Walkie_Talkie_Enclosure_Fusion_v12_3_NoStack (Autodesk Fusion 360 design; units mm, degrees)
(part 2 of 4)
sketch "Volume Down Switch Cage Anchor Sketch (1)" plane through (0, 0, 0) normal (0, 0, 1) x axis (1, 0, 0)
  line L1 (-31.5, -1.65) -> (-32, -1.65)
  line L2 (-31.15, -0.8) -> (-31.15, -1.3)
  line L3 (-32, -0.45) -> (-31.5, -0.45)
  line L4 (-32.35, -1.3) -> (-32.35, -0.8)
  arc A1 centre (-31.5, -1.3) radius 0.35 clockwise from (-31.15, -1.3) to (-31.5, -1.65)
  arc A2 centre (-31.5, -0.8) radius 0.35 clockwise from (-31.5, -0.45) to (-31.15, -0.8)
  arc A3 centre (-32, -0.8) radius 0.35 clockwise from (-32.35, -0.8) to (-32, -0.45)
  arc A4 centre (-32, -1.3) radius 0.35 clockwise from (-32, -1.65) to (-32.35, -1.3)
extrude "Extrude66" add sketch "Volume Down Switch Cage Anchor Sketch (1)" blind 5.59 from offset 2
sketch "Volume Down Switch Floor Sketch" plane through (0, 0, 0) normal (0, 0, 1) x axis (1, 0, 0)
  line L1 (-31.55, -11.35) -> (-36.65, -11.35)
  line L2 (-31.1, -1.1) -> (-31.1, -10.9)
  line L3 (-36.65, -0.65) -> (-31.55, -0.65)
  line L4 (-37.1, -10.9) -> (-37.1, -1.1)
  arc A1 centre (-31.55, -10.9) radius 0.45 clockwise from (-31.1, -10.9) to (-31.55, -11.35)
  arc A2 centre (-31.55, -1.1) radius 0.45 clockwise from (-31.55, -0.65) to (-31.1, -1.1)
  arc A3 centre (-36.65, -1.1) radius 0.45 clockwise from (-37.1, -1.1) to (-36.65, -0.65)
  arc A4 centre (-36.65, -10.9) radius 0.45 clockwise from (-36.65, -11.35) to (-37.1, -10.9)
extrude "Extrude67" add sketch "Volume Down Switch Floor Sketch" blind 0.55 from offset 7.49
sketch "Volume Down Switch Inward Backstop Sketch" plane through (0, 0, 0) normal (0, 0, 1) x axis (1, 0, 0)
  line L1 (-31.65, -11.35) -> (-31.85, -11.35)
  line L2 (-31.3, -1) -> (-31.3, -11)
  line L3 (-31.85, -0.65) -> (-31.65, -0.65)
  line L4 (-32.2, -11) -> (-32.2, -1)
  arc A1 centre (-31.65, -11) radius 0.35 clockwise from (-31.3, -11) to (-31.65, -11.35)
  arc A2 centre (-31.65, -1) radius 0.35 clockwise from (-31.65, -0.65) to (-31.3, -1)
  arc A3 centre (-31.85, -1) radius 0.35 clockwise from (-32.2, -1) to (-31.85, -0.65)
  arc A4 centre (-31.85, -11) radius 0.35 clockwise from (-31.85, -11.35) to (-32.2, -11)
extrude "Extrude68" add sketch "Volume Down Switch Inward Backstop Sketch" blind 4.51 from offset 7.49
sketch "Volume Down Switch Side Rail Sketch" plane through (0, 0, 0) normal (0, 0, 1) x axis (1, 0, 0)
  line L1 (-32.325, -11.35) -> (-36.675, -11.35)
  line L2 (-32.025, -10.85) -> (-32.025, -11.05)
  line L3 (-36.675, -10.55) -> (-32.325, -10.55)
  line L4 (-36.975, -11.05) -> (-36.975, -10.85)
  arc A1 centre (-32.325, -11.05) radius 0.3 clockwise from (-32.025, -11.05) to (-32.325, -11.35)
  arc A2 centre (-32.325, -10.85) radius 0.3 clockwise from (-32.325, -10.55) to (-32.025, -10.85)
  arc A3 centre (-36.675, -10.85) radius 0.3 clockwise from (-36.975, -10.85) to (-36.675, -10.55)
  arc A4 centre (-36.675, -11.05) radius 0.3 clockwise from (-36.675, -11.35) to (-36.975, -11.05)
extrude "Extrude69" add sketch "Volume Down Switch Side Rail Sketch" blind 4.51 from offset 7.49
sketch "Volume Down Switch Side Rail Sketch (1)" plane through (0, 0, 0) normal (0, 0, 1) x axis (1, 0, 0)
  line L1 (-32.325, -1.45) -> (-36.675, -1.45)
  line L2 (-32.025, -0.95) -> (-32.025, -1.15)
  line L3 (-36.675, -0.65) -> (-32.325, -0.65)
  line L4 (-36.975, -1.15) -> (-36.975, -0.95)
  arc A1 centre (-32.325, -1.15) radius 0.3 clockwise from (-32.025, -1.15) to (-32.325, -1.45)
  arc A2 centre (-32.325, -0.95) radius 0.3 clockwise from (-32.325, -0.65) to (-32.025, -0.95)
  arc A3 centre (-36.675, -0.95) radius 0.3 clockwise from (-36.975, -0.95) to (-36.675, -0.65)
  arc A4 centre (-36.675, -1.15) radius 0.3 clockwise from (-36.675, -1.45) to (-36.975, -1.15)
extrude "Extrude70" add sketch "Volume Down Switch Side Rail Sketch (1)" blind 4.51 from offset 7.49
sketch "Volume Down Switch Actuator Shoulder Sketch" plane through (0, 0, 0) normal (0, 0, 1) x axis (1, 0, 0)
  line L1 (-37.22, -11.35) -> (-37.28, -11.35)
  line L2 (-37, -0.87) -> (-37, -11.13)
  line L3 (-37.28, -0.65) -> (-37.22, -0.65)
  line L4 (-37.5, -11.13) -> (-37.5, -0.87)
  arc A1 centre (-37.22, -11.13) radius 0.22 clockwise from (-37, -11.13) to (-37.22, -11.35)
  arc A2 centre (-37.22, -0.87) radius 0.22 clockwise from (-37.22, -0.65) to (-37, -0.87)
  arc A3 centre (-37.28, -0.87) radius 0.22 clockwise from (-37.5, -0.87) to (-37.28, -0.65)
  arc A4 centre (-37.28, -11.13) radius 0.22 clockwise from (-37.28, -11.35) to (-37.5, -11.13)
extrude "Extrude71" add sketch "Volume Down Switch Actuator Shoulder Sketch" blind 4.51 from offset 7.49
sketch "Volume Down Actuator Passage Sketch" plane through (0, 0, 0) normal (1, 0, 0) x axis (0, 0, -1)
  line L1 (-14.4, -7.4) -> (-16, -7.4)
  line L2 (-13.8, -5.2) -> (-13.8, -6.8)
  line L3 (-16, -4.6) -> (-14.4, -4.6)
  line L4 (-16.6, -6.8) -> (-16.6, -5.2)
  arc A1 centre (-14.4, -6.8) radius 0.6 clockwise from (-13.8, -6.8) to (-14.4, -7.4)
  arc A2 centre (-14.4, -5.2) radius 0.6 clockwise from (-14.4, -4.6) to (-13.8, -5.2)
  arc A3 centre (-16, -5.2) radius 0.6 clockwise from (-16.6, -5.2) to (-16, -4.6)
  arc A4 centre (-16, -6.8) radius 0.6 clockwise from (-16, -7.4) to (-16.6, -6.8)
extrude "Extrude72" cut sketch "Volume Down Actuator Passage Sketch" blind -4.2 (= "-( 4.20 mm )") from offset -35.8
sketch "PCB Front Ledge Wall Trunk Sketch" plane through (0, 0, 0) normal (0, 0, 1) x axis (1, 0, 0)
  line L1 (-31.55, -45.04) -> (-33.95, -45.04)
  line L2 (-30.75, -39.84) -> (-30.75, -44.24)
  line L3 (-33.95, -39.04) -> (-31.55, -39.04)
  line L4 (-34.75, -44.24) -> (-34.75, -39.84)
  arc A1 centre (-31.55, -44.24) radius 0.8 clockwise from (-30.75, -44.24) to (-31.55, -45.04)
  arc A2 centre (-31.55, -39.84) radius 0.8 clockwise from (-31.55, -39.04) to (-30.75, -39.84)
  arc A3 centre (-33.95, -39.84) radius 0.8 clockwise from (-34.75, -39.84) to (-33.95, -39.04)
  arc A4 centre (-33.95, -44.24) radius 0.8 clockwise from (-33.95, -45.04) to (-34.75, -44.24)
extrude "Extrude73" add sketch "PCB Front Ledge Wall Trunk Sketch" blind 9.8 from offset 2
sketch "PCB Front Substrate Ledge Sketch" plane through (0, 0, 0) normal (0, 0, 1) x axis (1, 0, 0)
  line L1 (-28.3, -45.04) -> (-34.7, -45.04)
  line L2 (-27.5, -39.84) -> (-27.5, -44.24)
  line L3 (-34.7, -39.04) -> (-28.3, -39.04)
  line L4 (-35.5, -44.24) -> (-35.5, -39.84)
  arc A1 centre (-28.3, -44.24) radius 0.8 clockwise from (-27.5, -44.24) to (-28.3, -45.04)
  arc A2 centre (-28.3, -39.84) radius 0.8 clockwise from (-28.3, -39.04) to (-27.5, -39.84)
  arc A3 centre (-34.7, -39.84) radius 0.8 clockwise from (-35.5, -39.84) to (-34.7, -39.04)
  arc A4 centre (-34.7, -44.24) radius 0.8 clockwise from (-34.7, -45.04) to (-35.5, -44.24)
extrude "Extrude74" add sketch "PCB Front Substrate Ledge Sketch" blind 5.11 from offset 7.6
sketch "PCB Front Ledge Wall Trunk Sketch (1)" plane through (0, 0, 0) normal (0, 0, 1) x axis (1, 0, 0)
  line L1 (-31.55, -28.04) -> (-33.95, -28.04)
  line L2 (-30.75, -22.84) -> (-30.75, -27.24)
  line L3 (-33.95, -22.04) -> (-31.55, -22.04)
  line L4 (-34.75, -27.24) -> (-34.75, -22.84)
  arc A1 centre (-31.55, -27.24) radius 0.8 clockwise from (-30.75, -27.24) to (-31.55, -28.04)
  arc A2 centre (-31.55, -22.84) radius 0.8 clockwise from (-31.55, -22.04) to (-30.75, -22.84)
  arc A3 centre (-33.95, -22.84) radius 0.8 clockwise from (-34.75, -22.84) to (-33.95, -22.04)
  arc A4 centre (-33.95, -27.24) radius 0.8 clockwise from (-33.95, -28.04) to (-34.75, -27.24)
extrude "Extrude75" add sketch "PCB Front Ledge Wall Trunk Sketch (1)" blind 9.8 from offset 2
sketch "PCB Front Substrate Ledge Sketch (1)" plane through (0, 0, 0) normal (0, 0, 1) x axis (1, 0, 0)
  line L1 (-28.3, -28.04) -> (-34.7, -28.04)
  line L2 (-27.5, -22.84) -> (-27.5, -27.24)
  line L3 (-34.7, -22.04) -> (-28.3, -22.04)
  line L4 (-35.5, -27.24) -> (-35.5, -22.84)
  arc A1 centre (-28.3, -27.24) radius 0.8 clockwise from (-27.5, -27.24) to (-28.3, -28.04)
  arc A2 centre (-28.3, -22.84) radius 0.8 clockwise from (-28.3, -22.04) to (-27.5, -22.84)
  arc A3 centre (-34.7, -22.84) radius 0.8 clockwise from (-35.5, -22.84) to (-34.7, -22.04)
  arc A4 centre (-34.7, -27.24) radius 0.8 clockwise from (-34.7, -28.04) to (-35.5, -27.24)
extrude "Extrude76" add sketch "PCB Front Substrate Ledge Sketch (1)" blind 5.11 from offset 7.6
sketch "PCB Front Ledge Wall Trunk Sketch (2)" plane through (0, 0, 0) normal (0, 0, 1) x axis (1, 0, 0)
  line L1 (33.95, -45.04) -> (31.55, -45.04)
  line L2 (34.75, -39.84) -> (34.75, -44.24)
  line L3 (31.55, -39.04) -> (33.95, -39.04)
  line L4 (30.75, -44.24) -> (30.75, -39.84)
  arc A1 centre (33.95, -44.24) radius 0.8 clockwise from (34.75, -44.24) to (33.95, -45.04)
  arc A2 centre (33.95, -39.84) radius 0.8 clockwise from (33.95, -39.04) to (34.75, -39.84)
  arc A3 centre (31.55, -39.84) radius 0.8 clockwise from (30.75, -39.84) to (31.55, -39.04)
  arc A4 centre (31.55, -44.24) radius 0.8 clockwise from (31.55, -45.04) to (30.75, -44.24)
extrude "Extrude77" add sketch "PCB Front Ledge Wall Trunk Sketch (2)" blind 9.8 from offset 2
sketch "PCB Front Substrate Ledge Sketch (2)" plane through (0, 0, 0) normal (0, 0, 1) x axis (1, 0, 0)
  line L1 (34.7, -45.04) -> (28.3, -45.04)
  line L2 (35.5, -39.84) -> (35.5, -44.24)
  line L3 (28.3, -39.04) -> (34.7, -39.04)
  line L4 (27.5, -44.24) -> (27.5, -39.84)
  arc A1 centre (34.7, -44.24) radius 0.8 clockwise from (35.5, -44.24) to (34.7, -45.04)
  arc A2 centre (34.7, -39.84) radius 0.8 clockwise from (34.7, -39.04) to (35.5, -39.84)
  arc A3 centre (28.3, -39.84) radius 0.8 clockwise from (27.5, -39.84) to (28.3, -39.04)
  arc A4 centre (28.3, -44.24) radius 0.8 clockwise from (28.3, -45.04) to (27.5, -44.24)
extrude "Extrude78" add sketch "PCB Front Substrate Ledge Sketch (2)" blind 5.11 from offset 7.6
sketch "PCB Front Ledge Wall Trunk Sketch (3)" plane through (0, 0, 0) normal (0, 0, 1) x axis (1, 0, 0)
  line L1 (33.95, -28.04) -> (31.55, -28.04)
  line L2 (34.75, -22.84) -> (34.75, -27.24)
  line L3 (31.55, -22.04) -> (33.95, -22.04)
  line L4 (30.75, -27.24) -> (30.75, -22.84)
  arc A1 centre (33.95, -27.24) radius 0.8 clockwise from (34.75, -27.24) to (33.95, -28.04)
  arc A2 centre (33.95, -22.84) radius 0.8 clockwise from (33.95, -22.04) to (34.75, -22.84)
  arc A3 centre (31.55, -22.84) radius 0.8 clockwise from (30.75, -22.84) to (31.55, -22.04)
  arc A4 centre (31.55, -27.24) radius 0.8 clockwise from (31.55, -28.04) to (30.75, -27.24)
extrude "Extrude79" add sketch "PCB Front Ledge Wall Trunk Sketch (3)" blind 9.8 from offset 2
sketch "PCB Front Substrate Ledge Sketch (3)" plane through (0, 0, 0) normal (0, 0, 1) x axis (1, 0, 0)
  line L1 (34.7, -28.04) -> (28.3, -28.04)
  line L2 (35.5, -22.84) -> (35.5, -27.24)
  line L3 (28.3, -22.04) -> (34.7, -22.04)
  line L4 (27.5, -27.24) -> (27.5, -22.84)
  arc A1 centre (34.7, -27.24) radius 0.8 clockwise from (35.5, -27.24) to (34.7, -28.04)
  arc A2 centre (34.7, -22.84) radius 0.8 clockwise from (34.7, -22.04) to (35.5, -22.84)
  arc A3 centre (28.3, -22.84) radius 0.8 clockwise from (27.5, -22.84) to (28.3, -22.04)
  arc A4 centre (28.3, -27.24) radius 0.8 clockwise from (28.3, -28.04) to (27.5, -27.24)
extrude "Extrude80" add sketch "PCB Front Substrate Ledge Sketch (3)" blind 5.11 from offset 7.6
sketch "PCB X Edge Locator Sketch" plane through (0, 0, 0) normal (0, 0, 1) x axis (1, 0, 0)
  line L1 (-30.71, -45.54) -> (-31.21, -45.54)
  line L2 (-30.26, -38.99) -> (-30.26, -45.09)
  line L3 (-31.21, -38.54) -> (-30.71, -38.54)
  line L4 (-31.66, -45.09) -> (-31.66, -38.99)
  arc A1 centre (-30.71, -45.09) radius 0.45 clockwise from (-30.26, -45.09) to (-30.71, -45.54)
  arc A2 centre (-30.71, -38.99) radius 0.45 clockwise from (-30.71, -38.54) to (-30.26, -38.99)
  arc A3 centre (-31.21, -38.99) radius 0.45 clockwise from (-31.66, -38.99) to (-31.21, -38.54)
  arc A4 centre (-31.21, -45.09) radius 0.45 clockwise from (-31.21, -45.54) to (-31.66, -45.09)
extrude "Extrude81" add sketch "PCB X Edge Locator Sketch" blind 2 from offset 12.51
sketch "PCB X Edge Locator Sketch (1)" plane through (0, 0, 0) normal (0, 0, 1) x axis (1, 0, 0)
  line L1 (-30.71, -28.54) -> (-31.21, -28.54)
  line L2 (-30.26, -21.99) -> (-30.26, -28.09)
  line L3 (-31.21, -21.54) -> (-30.71, -21.54)
  line L4 (-31.66, -28.09) -> (-31.66, -21.99)
  arc A1 centre (-30.71, -28.09) radius 0.45 clockwise from (-30.26, -28.09) to (-30.71, -28.54)
  arc A2 centre (-30.71, -21.99) radius 0.45 clockwise from (-30.71, -21.54) to (-30.26, -21.99)
  arc A3 centre (-31.21, -21.99) radius 0.45 clockwise from (-31.66, -21.99) to (-31.21, -21.54)
  arc A4 centre (-31.21, -28.09) radius 0.45 clockwise from (-31.21, -28.54) to (-31.66, -28.09)
extrude "Extrude82" add sketch "PCB X Edge Locator Sketch (1)" blind 2 from offset 12.51
sketch "PCB X Edge Locator Sketch (2)" plane through (0, 0, 0) normal (0, 0, 1) x axis (1, 0, 0)
  line L1 (31.21, -45.54) -> (30.71, -45.54)
  line L2 (31.66, -38.99) -> (31.66, -45.09)
  line L3 (30.71, -38.54) -> (31.21, -38.54)
  line L4 (30.26, -45.09) -> (30.26, -38.99)
  arc A1 centre (31.21, -45.09) radius 0.45 clockwise from (31.66, -45.09) to (31.21, -45.54)
  arc A2 centre (31.21, -38.99) radius 0.45 clockwise from (31.21, -38.54) to (31.66, -38.99)
  arc A3 centre (30.71, -38.99) radius 0.45 clockwise from (30.26, -38.99) to (30.71, -38.54)
  arc A4 centre (30.71, -45.09) radius 0.45 clockwise from (30.71, -45.54) to (30.26, -45.09)
extrude "Extrude83" add sketch "PCB X Edge Locator Sketch (2)" blind 2 from offset 12.51
sketch "PCB X Edge Locator Sketch (3)" plane through (0, 0, 0) normal (0, 0, 1) x axis (1, 0, 0)
  line L1 (31.21, -28.54) -> (30.71, -28.54)
  line L2 (31.66, -21.99) -> (31.66, -28.09)
  line L3 (30.71, -21.54) -> (31.21, -21.54)
  line L4 (30.26, -28.09) -> (30.26, -21.99)
  arc A1 centre (31.21, -28.09) radius 0.45 clockwise from (31.66, -28.09) to (31.21, -28.54)
  arc A2 centre (31.21, -21.99) radius 0.45 clockwise from (31.21, -21.54) to (31.66, -21.99)
  arc A3 centre (30.71, -21.99) radius 0.45 clockwise from (30.26, -21.99) to (30.71, -21.54)
  arc A4 centre (30.71, -28.09) radius 0.45 clockwise from (30.71, -28.54) to (30.26, -28.09)
extrude "Extrude84" add sketch "PCB X Edge Locator Sketch (3)" blind 2 from offset 12.51
sketch "Measured-Lead Cable Channel Rail Sketch" plane through (0, 0, 0) normal (0, 0, 1) x axis (1, 0, 0)
  line L1 (23.9, -32.04) -> (23.6, -32.04)
  line L2 (24.35, 25.52) -> (24.35, -31.59)
  line L3 (23.6, 25.97) -> (23.9, 25.97)
  line L4 (23.15, -31.59) -> (23.15, 25.52)
  arc A1 centre (23.9, -31.59) radius 0.45 clockwise from (24.35, -31.59) to (23.9, -32.04)
  arc A2 centre (23.9, 25.52) radius 0.45 clockwise from (23.9, 25.97) to (24.35, 25.52)
  arc A3 centre (23.6, 25.52) radius 0.45 clockwise from (23.15, 25.52) to (23.6, 25.97)
  arc A4 centre (23.6, -31.59) radius 0.45 clockwise from (23.6, -32.04) to (23.15, -31.59)
extrude "Extrude85" add sketch "Measured-Lead Cable Channel Rail Sketch" blind 3.4 from offset 2
sketch "Measured-Lead Cable Channel Rail Sketch (1)" plane through (0, 0, 0) normal (0, 0, 1) x axis (1, 0, 0)
  line L1 (30.4, -32.04) -> (30.1, -32.04)
  line L2 (30.85, 25.52) -> (30.85, -31.59)
  line L3 (30.1, 25.97) -> (30.4, 25.97)
  line L4 (29.65, -31.59) -> (29.65, 25.52)
  arc A1 centre (30.4, -31.59) radius 0.45 clockwise from (30.85, -31.59) to (30.4, -32.04)
  arc A2 centre (30.4, 25.52) radius 0.45 clockwise from (30.4, 25.97) to (30.85, 25.52)
  arc A3 centre (30.1, 25.52) radius 0.45 clockwise from (29.65, 25.52) to (30.1, 25.97)
  arc A4 centre (30.1, -31.59) radius 0.45 clockwise from (30.1, -32.04) to (29.65, -31.59)
extrude "Extrude86" add sketch "Measured-Lead Cable Channel Rail Sketch (1)" blind 3.4 from offset 2
sketch "Open-End Cable Retaining Tab Sketch" plane through (0, 0, 0) normal (0, 0, 1) x axis (1, 0, 0)
  line L1 (25.6, -19.2) -> (24.9, -19.2)
  line L2 (26.15, -17.35) -> (26.15, -18.65)
  line L3 (24.9, -16.8) -> (25.6, -16.8)
  line L4 (24.35, -18.65) -> (24.35, -17.35)
  arc A1 centre (25.6, -18.65) radius 0.55 clockwise from (26.15, -18.65) to (25.6, -19.2)
  arc A2 centre (25.6, -17.35) radius 0.55 clockwise from (25.6, -16.8) to (26.15, -17.35)
  arc A3 centre (24.9, -17.35) radius 0.55 clockwise from (24.35, -17.35) to (24.9, -16.8)
  arc A4 centre (24.9, -18.65) radius 0.55 clockwise from (24.9, -19.2) to (24.35, -18.65)
extrude "Extrude87" add sketch "Open-End Cable Retaining Tab Sketch" blind 0.8 from offset 5.05
sketch "Open-End Cable Retaining Tab Sketch (1)" plane through (0, 0, 0) normal (0, 0, 1) x axis (1, 0, 0)
  line L1 (29.1, -19.2) -> (28.4, -19.2)
  line L2 (29.65, -17.35) -> (29.65, -18.65)
  line L3 (28.4, -16.8) -> (29.1, -16.8)
  line L4 (27.85, -18.65) -> (27.85, -17.35)
  arc A1 centre (29.1, -18.65) radius 0.55 clockwise from (29.65, -18.65) to (29.1, -19.2)
  arc A2 centre (29.1, -17.35) radius 0.55 clockwise from (29.1, -16.8) to (29.65, -17.35)
  arc A3 centre (28.4, -17.35) radius 0.55 clockwise from (27.85, -17.35) to (28.4, -16.8)
  arc A4 centre (28.4, -18.65) radius 0.55 clockwise from (28.4, -19.2) to (27.85, -18.65)
extrude "Extrude88" add sketch "Open-End Cable Retaining Tab Sketch (1)" blind 0.8 from offset 5.05
sketch "Open-End Cable Retaining Tab Sketch (2)" plane through (0, 0, 0) normal (0, 0, 1) x axis (1, 0, 0)
  line L1 (25.6, 0.8) -> (24.9, 0.8)
  line L2 (26.15, 2.65) -> (26.15, 1.35)
  line L3 (24.9, 3.2) -> (25.6, 3.2)
  line L4 (24.35, 1.35) -> (24.35, 2.65)
  arc A1 centre (25.6, 1.35) radius 0.55 clockwise from (26.15, 1.35) to (25.6, 0.8)
  arc A2 centre (25.6, 2.65) radius 0.55 clockwise from (25.6, 3.2) to (26.15, 2.65)
  arc A3 centre (24.9, 2.65) radius 0.55 clockwise from (24.35, 2.65) to (24.9, 3.2)
  arc A4 centre (24.9, 1.35) radius 0.55 clockwise from (24.9, 0.8) to (24.35, 1.35)
extrude "Extrude89" add sketch "Open-End Cable Retaining Tab Sketch (2)" blind 0.8 from offset 5.05
sketch "Open-End Cable Retaining Tab Sketch (3)" plane through (0, 0, 0) normal (0, 0, 1) x axis (1, 0, 0)
  line L1 (29.1, 0.8) -> (28.4, 0.8)
  line L2 (29.65, 2.65) -> (29.65, 1.35)
  line L3 (28.4, 3.2) -> (29.1, 3.2)
  line L4 (27.85, 1.35) -> (27.85, 2.65)
  arc A1 centre (29.1, 1.35) radius 0.55 clockwise from (29.65, 1.35) to (29.1, 0.8)
  arc A2 centre (29.1, 2.65) radius 0.55 clockwise from (29.1, 3.2) to (29.65, 2.65)
  arc A3 centre (28.4, 2.65) radius 0.55 clockwise from (27.85, 2.65) to (28.4, 3.2)
  arc A4 centre (28.4, 1.35) radius 0.55 clockwise from (28.4, 0.8) to (27.85, 1.35)
extrude "Extrude90" add sketch "Open-End Cable Retaining Tab Sketch (3)" blind 0.8 from offset 5.05
sketch "Open-End Cable Retaining Tab Sketch (4)" plane through (0, 0, 0) normal (0, 0, 1) x axis (1, 0, 0)
  line L1 (25.6, 16.8) -> (24.9, 16.8)
  line L2 (26.15, 18.65) -> (26.15, 17.35)
  line L3 (24.9, 19.2) -> (25.6, 19.2)
  line L4 (24.35, 17.35) -> (24.35, 18.65)
  arc A1 centre (25.6, 17.35) radius 0.55 clockwise from (26.15, 17.35) to (25.6, 16.8)
  arc A2 centre (25.6, 18.65) radius 0.55 clockwise from (25.6, 19.2) to (26.15, 18.65)
  arc A3 centre (24.9, 18.65) radius 0.55 clockwise from (24.35, 18.65) to (24.9, 19.2)
  arc A4 centre (24.9, 17.35) radius 0.55 clockwise from (24.9, 16.8) to (24.35, 17.35)
extrude "Extrude91" add sketch "Open-End Cable Retaining Tab Sketch (4)" blind 0.8 from offset 5.05
sketch "Open-End Cable Retaining Tab Sketch (5)" plane through (0, 0, 0) normal (0, 0, 1) x axis (1, 0, 0)
  line L1 (29.1, 16.8) -> (28.4, 16.8)
  line L2 (29.65, 18.65) -> (29.65, 17.35)
  line L3 (28.4, 19.2) -> (29.1, 19.2)
  line L4 (27.85, 17.35) -> (27.85, 18.65)
  arc A1 centre (29.1, 17.35) radius 0.55 clockwise from (29.65, 17.35) to (29.1, 16.8)
  arc A2 centre (29.1, 18.65) radius 0.55 clockwise from (29.1, 19.2) to (29.65, 18.65)
  arc A3 centre (28.4, 18.65) radius 0.55 clockwise from (27.85, 18.65) to (28.4, 19.2)
  arc A4 centre (28.4, 17.35) radius 0.55 clockwise from (28.4, 16.8) to (27.85, 17.35)
extrude "Extrude92" add sketch "Open-End Cable Retaining Tab Sketch (5)" blind 0.8 from offset 5.05
sketch "No-Stack Battery Rounded Front Pad Sketch" plane through (0, 0, 0) normal (0, 0, 1) x axis (1, 0, 0)
  line L1 (-25, 31.5) -> (-28, 31.5)
  line L2 (-24, 37.5) -> (-24, 32.5)
  line L3 (-28, 38.5) -> (-25, 38.5)
  line L4 (-29, 32.5) -> (-29, 37.5)
  arc A1 centre (-25, 32.5) radius 1 clockwise from (-24, 32.5) to (-25, 31.5)
  arc A2 centre (-25, 37.5) radius 1 clockwise from (-25, 38.5) to (-24, 37.5)
  arc A3 centre (-28, 37.5) radius 1 clockwise from (-29, 37.5) to (-28, 38.5)
  arc A4 centre (-28, 32.5) radius 1 clockwise from (-28, 31.5) to (-29, 32.5)
extrude "Extrude93" add sketch "No-Stack Battery Rounded Front Pad Sketch" blind 5.9 from offset 2
sketch "No-Stack Battery Rounded Front Pad Sketch (1)" plane through (0, 0, 0) normal (0, 0, 1) x axis (1, 0, 0)
  line L1 (-25, 51.5) -> (-28, 51.5)
  line L2 (-24, 57.5) -> (-24, 52.5)
  line L3 (-28, 58.5) -> (-25, 58.5)
  line L4 (-29, 52.5) -> (-29, 57.5)
  arc A1 centre (-25, 52.5) radius 1 clockwise from (-24, 52.5) to (-25, 51.5)
  arc A2 centre (-25, 57.5) radius 1 clockwise from (-25, 58.5) to (-24, 57.5)
  arc A3 centre (-28, 57.5) radius 1 clockwise from (-29, 57.5) to (-28, 58.5)
  arc A4 centre (-28, 52.5) radius 1 clockwise from (-28, 51.5) to (-29, 52.5)
extrude "Extrude94" add sketch "No-Stack Battery Rounded Front Pad Sketch (1)" blind 5.9 from offset 2
sketch "No-Stack Battery Rounded Front Pad Sketch (2)" plane through (0, 0, 0) normal (0, 0, 1) x axis (1, 0, 0)
  line L1 (28, 31.5) -> (25, 31.5)
  line L2 (29, 37.5) -> (29, 32.5)
  line L3 (25, 38.5) -> (28, 38.5)
  line L4 (24, 32.5) -> (24, 37.5)
  arc A1 centre (28, 32.5) radius 1 clockwise from (29, 32.5) to (28, 31.5)
  arc A2 centre (28, 37.5) radius 1 clockwise from (28, 38.5) to (29, 37.5)
  arc A3 centre (25, 37.5) radius 1 clockwise from (24, 37.5) to (25, 38.5)
  arc A4 centre (25, 32.5) radius 1 clockwise from (25, 31.5) to (24, 32.5)
extrude "Extrude95" add sketch "No-Stack Battery Rounded Front Pad Sketch (2)" blind 5.9 from offset 2
sketch "No-Stack Battery Rounded Front Pad Sketch (3)" plane through (0, 0, 0) normal (0, 0, 1) x axis (1, 0, 0)
  line L1 (28, 51.5) -> (25, 51.5)
  line L2 (29, 57.5) -> (29, 52.5)
  line L3 (25, 58.5) -> (28, 58.5)
  line L4 (24, 52.5) -> (24, 57.5)
  arc A1 centre (28, 52.5) radius 1 clockwise from (29, 52.5) to (28, 51.5)
  arc A2 centre (28, 57.5) radius 1 clockwise from (28, 58.5) to (29, 57.5)
  arc A3 centre (25, 57.5) radius 1 clockwise from (24, 57.5) to (25, 58.5)
  arc A4 centre (25, 52.5) radius 1 clockwise from (25, 51.5) to (24, 52.5)
extrude "Extrude96" add sketch "No-Stack Battery Rounded Front Pad Sketch (3)" blind 5.9 from offset 2
sketch "Front Screw Posts" plane through (0, 0, 0) normal (0, 0, 1) x axis (1, 0, 0)
  circle C1 centre (-33.4, -56) radius 2.8
  circle C2 centre (-33.4, 56) radius 2.8
  circle C3 centre (33.4, -56) radius 2.8
  circle C4 centre (33.4, 56) radius 2.8
extrude "Extrude97" add sketch "Front Screw Posts" blind 2 from offset 10
sketch "M2.5 Pilot Holes" plane through (0, 0, 0) normal (0, 0, 1) x axis (1, 0, 0)
  circle C1 centre (-33.4, -56) radius 1.05
  circle C2 centre (-33.4, 56) radius 1.05
  circle C3 centre (33.4, -56) radius 1.05
  circle C4 centre (33.4, 56) radius 1.05
extrude "Extrude98" cut sketch "M2.5 Pilot Holes" blind 2 from offset 10.5
sketch "Back Outer Housing" plane through (0, 0, 0) normal (0, 0, 1) x axis (1, 0, 0)
  line L1 (14, -75) -> (-14, -75)
  line L2 (39, 50) -> (39, -50)
  line L3 (-14, 75) -> (14, 75)
  line L4 (-39, -50) -> (-39, 50)
  arc A1 centre (14, -50) radius 25 clockwise from (39, -50) to (14, -75)
  arc A2 centre (14, 50) radius 25 clockwise from (14, 75) to (39, 50)
  arc A3 centre (-14, 50) radius 25 clockwise from (-39, 50) to (-14, 75)
  arc A4 centre (-14, -50) radius 25 clockwise from (-14, -75) to (-39, -50)
extrude "Extrude1" new body sketch "Back Outer Housing" blind 12 from offset 12
fillet "Fillet1" radius 10
sketch "Back Shell Concealed Seam Rabbet Sketch" plane through (0, 0, 0) normal (0, 0, 1) x axis (1, 0, 0)
  line L1 (14, -76) -> (-14, -76)
  line L2 (40, 50) -> (40, -50)
  line L3 (-14, 76) -> (14, 76)
  line L4 (-40, -50) -> (-40, 50)
  line L5 (14, -73.8) -> (-14, -73.8)
  line L6 (37.8, 50) -> (37.8, -50)
  line L7 (-14, 73.8) -> (14, 73.8)
  line L8 (-37.8, -50) -> (-37.8, 50)
  arc A1 centre (14, -50) radius 26 clockwise from (40, -50) to (14, -76)
  arc A2 centre (14, 50) radius 26 clockwise from (14, 76) to (40, 50)
  arc A3 centre (-14, 50) radius 26 clockwise from (-40, 50) to (-14, 76)
  arc A4 centre (-14, -50) radius 26 clockwise from (-14, -76) to (-40, -50)
  arc A5 centre (14, -50) radius 23.8 clockwise from (37.8, -50) to (14, -73.8)
  arc A6 centre (14, 50) radius 23.8 clockwise from (14, 73.8) to (37.8, 50)
  arc A7 centre (-14, 50) radius 23.8 clockwise from (-37.8, 50) to (-14, 73.8)
  arc A8 centre (-14, -50) radius 23.8 clockwise from (-14, -73.8) to (-37.8, -50)
extrude "Extrude2" cut sketch "Back Shell Concealed Seam Rabbet Sketch" blind 1.65 from offset 11.8
sketch "Back Cavity" plane through (0, 0, 0) normal (0, 0, 1) x axis (1, 0, 0)
  line L1 (14, -72.8) -> (-14, -72.8)
  line L2 (36.8, 50) -> (36.8, -50)
  line L3 (-14, 72.8) -> (14, 72.8)
  line L4 (-36.8, -50) -> (-36.8, 50)
  arc A1 centre (14, -50) radius 22.8 clockwise from (36.8, -50) to (14, -72.8)
  arc A2 centre (14, 50) radius 22.8 clockwise from (14, 72.8) to (36.8, 50)
  arc A3 centre (-14, 50) radius 22.8 clockwise from (-36.8, 50) to (-14, 72.8)
  arc A4 centre (-14, -50) radius 22.8 clockwise from (-14, -72.8) to (-36.8, -50)
extrude "Extrude3" new body sketch "Back Cavity" blind 10 from offset 11.8
fillet "Fillet2" radius 7.8
combine "Combine1"
sketch "Rear Palm Saddle Sketch" plane through (0, 0, 0) normal (0, 0, 1) x axis (1, 0, 0)
  line L1 (0.2, -47) -> (-0.2, -47)
  line L2 (22, 11.2) -> (22, -25.2)
  line L3 (-0.2, 33) -> (0.2, 33)
  line L4 (-22, -25.2) -> (-22, 11.2)
  arc A1 centre (0.2, -25.2) radius 21.8 clockwise from (22, -25.2) to (0.2, -47)
  arc A2 centre (0.2, 11.2) radius 21.8 clockwise from (0.2, 33) to (22, 11.2)
  arc A3 centre (-0.2, 11.2) radius 21.8 clockwise from (-22, 11.2) to (-0.2, 33)
  arc A4 centre (-0.2, -25.2) radius 21.8 clockwise from (-0.2, -47) to (-22, -25.2)
extrude "Extrude4" cut sketch "Rear Palm Saddle Sketch" blind -0.7 (= "-( 0.70 mm )") from offset 24.05
sketch "Sketch5" plane through (0, 0, 0) normal (0, 0, 1) x axis (1, 0, 0)
  line L1 (-20.9973, -49.4649) -> (-19.643, -54.535)
  line L2 (-19.7281, -49.4649) -> (-20.9973, -49.4649)
  line L3 (-19.2007, -51.7822) -> (-19.7281, -49.4649)
  curve K1 (-19.0679, -52.5002) -> (-19.2007, -51.7822)
  curve K2 (-18.9489, -53.2692) -> (-19.0679, -52.5002)
  curve K3 (-18.9352, -53.3611) -> (-18.9489, -53.2692)
  curve K4 (-18.9216, -53.2692) -> (-18.9352, -53.3611)
  curve K5 (-18.7923, -52.5002) -> (-18.9216, -53.2692)
  curve K6 (-18.646, -51.7822) -> (-18.7923, -52.5002)
  line L4 (-18.0846, -49.4649) -> (-18.646, -51.7822)
  line L5 (-16.9038, -49.4649) -> (-18.0846, -49.4649)
  line L6 (-16.3423, -51.7822) -> (-16.9038, -49.4649)
  curve K7 (-16.1977, -52.5002) -> (-16.3423, -51.7822)
  curve K8 (-16.0667, -53.2692) -> (-16.1977, -52.5002)
  curve K9 (-16.0531, -53.3543) -> (-16.0667, -53.2692)
  curve K10 (-16.0395, -53.2692) -> (-16.0531, -53.3543)
  curve K11 (-15.9221, -52.5002) -> (-16.0395, -53.2692)
  curve K12 (-15.7877, -51.7822) -> (-15.9221, -52.5002)
  line L7 (-15.2603, -49.4649) -> (-15.7877, -51.7822)
  line L8 (-13.9876, -49.4649) -> (-15.2603, -49.4649)
  line L9 (-15.3453, -54.535) -> (-13.9876, -49.4649)
  line L10 (-16.6554, -54.535) -> (-15.3453, -54.535)
  line L11 (-17.2713, -52.1191) -> (-16.6554, -54.535)
  curve K13 (-17.4652, -51.1084) -> (-17.2713, -52.1191)
  curve K14 (-17.4993, -50.8805) -> (-17.4652, -51.1084)
  curve K15 (-17.5265, -51.0948) -> (-17.4993, -50.8805)
  curve K16 (-17.7137, -52.1191) -> (-17.5265, -51.0948)
  line L12 (-18.333, -54.535) -> (-17.7137, -52.1191)
  line L13 (-19.643, -54.535) -> (-18.333, -54.535)
  line L14 (-12.7116, -49.4649) -> (-14.4164, -54.535)
  line L15 (-11.1804, -49.4649) -> (-12.7116, -49.4649)
  line L16 (-9.428, -54.535) -> (-11.1804, -49.4649)
  line L17 (-10.7176, -54.535) -> (-9.428, -54.535)
  line L18 (-11.0749, -53.4257) -> (-10.7176, -54.535)
  line L19 (-12.7967, -53.4257) -> (-11.0749, -53.4257)
  line L20 (-13.1404, -54.535) -> (-12.7967, -53.4257)
  line L21 (-14.4164, -54.535) -> (-13.1404, -54.535)
  line L22 (-11.4526, -52.2484) -> (-11.3608, -52.541)
  curve K17 (-11.7725, -51.1152) -> (-11.4526, -52.2484)
  curve K18 (-11.9596, -50.3734) -> (-11.7725, -51.1152)
  curve K19 (-12.1332, -51.1187) -> (-11.9596, -50.3734)
  curve K20 (-12.4292, -52.2484) -> (-12.1332, -51.1187)
  line L23 (-12.5211, -52.541) -> (-12.4292, -52.2484)
  line L24 (-11.3608, -52.541) -> (-12.5211, -52.541)
  line L25 (-9.0718, -49.4649) -> (-9.0718, -54.535)
  line L26 (-7.9199, -49.4649) -> (-9.0718, -49.4649)
  line L27 (-7.9199, -53.5902) -> (-7.9199, -49.4649)
  line L28 (-5.7798, -53.5902) -> (-7.9199, -53.5902)
  line L29 (-5.7798, -54.535) -> (-5.7798, -53.5902)
  line L30 (-9.0718, -54.535) -> (-5.7798, -54.535)
  line L31 (-5.3516, -49.4649) -> (-5.3516, -54.535)
  line L32 (-4.2015, -49.4649) -> (-5.3516, -49.4649)
  line L33 (-4.2015, -50.7512) -> (-4.2015, -49.4649)
  line L34 (-4.2219, -51.9557) -> (-4.2015, -50.7512)
  curve K21 (-4.198, -51.9149) -> (-4.2219, -51.9557)
  curve K22 (-3.8731, -51.4232) -> (-4.198, -51.9149)
  curve K23 (-3.4494, -50.8702) -> (-3.8731, -51.4232)
  line L35 (-2.2891, -49.4649) -> (-3.4494, -50.8702)
  line L36 (-0.8974, -49.4649) -> (-2.2891, -49.4649)
  line L37 (-2.7519, -51.6563) -> (-0.8974, -49.4649)
  line L38 (-0.8293, -54.535) -> (-2.7519, -51.6563)
  line L39 (-2.187, -54.535) -> (-0.8293, -54.535)
  line L40 (-3.5447, -52.4117) -> (-2.187, -54.535)
  line L41 (-4.2015, -53.1467) -> (-3.5447, -52.4117)
  line L42 (-4.2015, -54.535) -> (-4.2015, -53.1467)
  line L43 (-5.3516, -54.535) -> (-4.2015, -54.535)
  line L44 (0.6822, -54.535) -> (0.6822, -49.4649)
  line L45 (-0.4697, -54.535) -> (0.6822, -54.535)
  line L46 (-0.4697, -49.4649) -> (-0.4697, -54.535)
  line L47 (0.6822, -49.4649) -> (-0.4697, -49.4649)
  line L48 (1.2895, -49.4649) -> (1.2895, -54.535)
  line L49 (4.7712, -49.4649) -> (1.2895, -49.4649)
  line L50 (4.7712, -50.4097) -> (4.7712, -49.4649)
  line L51 (2.4414, -50.4097) -> (4.7712, -50.4097)
  line L52 (2.4414, -51.5108) -> (2.4414, -50.4097)
  line L53 (4.5879, -51.5108) -> (2.4414, -51.5108)
  line L54 (4.5879, -52.4367) -> (4.5879, -51.5108)
  line L55 (2.4414, -52.4367) -> (4.5879, -52.4367)
  line L56 (2.4414, -53.5902) -> (2.4414, -52.4367)
  line L57 (4.7711, -53.5902) -> (2.4414, -53.5902)
  line L58 (4.7711, -54.535) -> (4.7711, -53.5902)
  line L59 (1.2895, -54.535) -> (4.7711, -54.535)
  curve K24 (8.2883, -54.2889) -> (9.4502, -54.6031)
  curve K25 (7.4839, -53.3912) -> (8.2883, -54.2889)
  curve K26 (7.19, -52.0034) -> (7.4839, -53.3912)
  curve K27 (7.4839, -50.6119) -> (7.19, -52.0034)
  curve K28 (8.2883, -49.7126) -> (7.4839, -50.6119)
  curve K29 (9.4502, -49.3969) -> (8.2883, -49.7126)
  curve K30 (10.6105, -49.7126) -> (9.4502, -49.3969)
  curve K31 (11.4116, -50.6119) -> (10.6105, -49.7126)
  curve K32 (11.7039, -52.0034) -> (11.4116, -50.6119)
  curve K33 (11.4116, -53.3913) -> (11.7039, -52.0034)
  curve K34 (10.6105, -54.2889) -> (11.4116, -53.3913)
  curve K35 (9.4502, -54.6031) -> (10.6105, -54.2889)
  curve K36 (10.2599, -53.7554) -> (9.4502, -53.9826)
  curve K37 (10.8335, -53.0855) -> (10.2599, -53.7554)
  curve K38 (11.0461, -52.0034) -> (10.8335, -53.0855)
  curve K39 (10.8335, -50.9145) -> (11.0461, -52.0034)
  curve K40 (10.2599, -50.2445) -> (10.8335, -50.9145)
  curve K41 (9.4502, -50.0173) -> (10.2599, -50.2445)
  curve K42 (8.6358, -50.2462) -> (9.4502, -50.0173)
  curve K43 (8.0605, -50.9177) -> (8.6358, -50.2462)
  curve K44 (7.8478, -52.0034) -> (8.0605, -50.9177)
  curve K45 (8.0605, -53.0839) -> (7.8478, -52.0034)
  curve K46 (8.6358, -53.7537) -> (8.0605, -53.0839)
  curve K47 (9.4502, -53.9826) -> (8.6358, -53.7537)
  line L60 (12.6604, -49.4649) -> (12.6604, -54.535)
  line L61 (13.4498, -49.4649) -> (12.6604, -49.4649)
  line L62 (15.4812, -52.6635) -> (13.4498, -49.4649)
  curve K48 (15.682, -52.9919) -> (15.4812, -52.6635)
  curve K49 (15.9304, -53.4427) -> (15.682, -52.9919)
  curve K50 (16.0801, -53.732) -> (15.9304, -53.4427)
  curve K51 (16.0597, -53.4189) -> (16.0801, -53.732)
  curve K52 (16.0393, -52.9187) -> (16.0597, -53.4189)
  curve K53 (16.0359, -52.5308) -> (16.0393, -52.9187)
  line L63 (16.0359, -49.4649) -> (16.0359, -52.5308)
  line L64 (16.7096, -49.4649) -> (16.0359, -49.4649)
  line L65 (16.7096, -54.535) -> (16.7096, -49.4649)
  line L66 (15.9168, -54.535) -> (16.7096, -54.535)
  line L67 (14.1031, -51.6869) -> (15.9168, -54.535)
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extrude "Extrude5" cut sketch "Sketch5" blind -0.4 (= "-( 0.40 mm )") from offset 24.05
sketch "Designed in Los Angeles Rear Tagline" plane through (0, 0, 0) normal (0, 0, 1) x axis (1, 0, 0)
  dimension "d381" = 1.6
extrude "Extrude6" cut sketch "Designed in Los Angeles Rear Tagline" blind -0.3 (= "-( 0.30 mm )") from offset 24.05
sketch "PTT Interaction Field Sketch" plane through (0, 0, 0) normal (1, 0, 0) x axis (0, 0, -1)
  line L1 (-11.9, -17.5) -> (-12.1, -17.5)
  line L2 (-5.1, 34.7) -> (-5.1, -10.7)
  line L3 (-12.1, 41.5) -> (-11.9, 41.5)
  line L4 (-18.9, -10.7) -> (-18.9, 34.7)
  arc A1 centre (-11.9, -10.7) radius 6.8 clockwise from (-5.1, -10.7) to (-11.9, -17.5)
  arc A2 centre (-11.9, 34.7) radius 6.8 clockwise from (-11.9, 41.5) to (-5.1, 34.7)
  arc A3 centre (-12.1, 34.7) radius 6.8 clockwise from (-18.9, 34.7) to (-12.1, 41.5)
  arc A4 centre (-12.1, -10.7) radius 6.8 clockwise from (-12.1, -17.5) to (-18.9, -10.7)
extrude "Extrude7" cut sketch "PTT Interaction Field Sketch" blind -0.75 (= "-( 0.75 mm )") from offset 39.2
sketch "Unified Volume Interaction Field Sketch" plane through (0, 0, 0) normal (1, 0, 0) x axis (0, 0, -1)
  line L1 (-11.9, -21.25) -> (-12.1, -21.25)
  line L2 (-5.1, 31.45) -> (-5.1, -14.45)
  line L3 (-12.1, 38.25) -> (-11.9, 38.25)
  line L4 (-18.9, -14.45) -> (-18.9, 31.45)
  arc A1 centre (-11.9, -14.45) radius 6.8 clockwise from (-5.1, -14.45) to (-11.9, -21.25)
  arc A2 centre (-11.9, 31.45) radius 6.8 clockwise from (-11.9, 38.25) to (-5.1, 31.45)
  arc A3 centre (-12.1, 31.45) radius 6.8 clockwise from (-18.9, 31.45) to (-12.1, 38.25)
  arc A4 centre (-12.1, -14.45) radius 6.8 clockwise from (-12.1, -21.25) to (-18.9, -14.45)
extrude "Extrude8" cut sketch "Unified Volume Interaction Field Sketch" blind 0.75 from offset -39.2
sketch "Left PTT Through Opening Sketch" plane through (0, 0, 0) normal (1, 0, 0) x axis (0, 0, -1)
  line L1 (-11.9, -13.2) -> (-12.1, -13.2)
  line L2 (-7.5, 32.8) -> (-7.5, -8.8)
  line L3 (-12.1, 37.2) -> (-11.9, 37.2)
  line L4 (-16.5, -8.8) -> (-16.5, 32.8)
  arc A1 centre (-11.9, -8.8) radius 4.4 clockwise from (-7.5, -8.8) to (-11.9, -13.2)
  arc A2 centre (-11.9, 32.8) radius 4.4 clockwise from (-11.9, 37.2) to (-7.5, 32.8)
  arc A3 centre (-12.1, 32.8) radius 4.4 clockwise from (-16.5, 32.8) to (-12.1, 37.2)
  arc A4 centre (-12.1, -8.8) radius 4.4 clockwise from (-12.1, -13.2) to (-16.5, -8.8)
extrude "Extrude9" cut sketch "Left PTT Through Opening Sketch" blind 40
sketch "Volume Up Through Opening Sketch" plane through (0, 0, 0) normal (1, 0, 0) x axis (0, 0, -1)
  line L1 (-11.9, 15.15) -> (-12.1, 15.15)
  line L2 (-7.8, 26.75) -> (-7.8, 19.25)
  line L3 (-12.1, 30.85) -> (-11.9, 30.85)
  line L4 (-16.2, 19.25) -> (-16.2, 26.75)
  arc A1 centre (-11.9, 19.25) radius 4.1 clockwise from (-7.8, 19.25) to (-11.9, 15.15)
  arc A2 centre (-11.9, 26.75) radius 4.1 clockwise from (-11.9, 30.85) to (-7.8, 26.75)
  arc A3 centre (-12.1, 26.75) radius 4.1 clockwise from (-16.2, 26.75) to (-12.1, 30.85)
  arc A4 centre (-12.1, 19.25) radius 4.1 clockwise from (-12.1, 15.15) to (-16.2, 19.25)
extrude "Extrude10" cut sketch "Volume Up Through Opening Sketch" blind -40 (= "-( 40.00 mm )")
sketch "Volume Down Through Opening Sketch" plane through (0, 0, 0) normal (1, 0, 0) x axis (0, 0, -1)
  line L1 (-11.9, -13.85) -> (-12.1, -13.85)
  line L2 (-7.8, -2.25) -> (-7.8, -9.75)
  line L3 (-12.1, 1.85) -> (-11.9, 1.85)
  line L4 (-16.2, -9.75) -> (-16.2, -2.25)
  arc A1 centre (-11.9, -9.75) radius 4.1 clockwise from (-7.8, -9.75) to (-11.9, -13.85)
  arc A2 centre (-11.9, -2.25) radius 4.1 clockwise from (-11.9, 1.85) to (-7.8, -2.25)
  arc A3 centre (-12.1, -2.25) radius 4.1 clockwise from (-16.2, -2.25) to (-12.1, 1.85)
  arc A4 centre (-12.1, -9.75) radius 4.1 clockwise from (-12.1, -13.85) to (-16.2, -9.75)
extrude "Extrude11" cut sketch "Volume Down Through Opening Sketch" blind -40 (= "-( 40.00 mm )")
sketch "USB-C Full-Seating Local Wall Recess Sketch" plane through (0, 0, 0) normal (1, 0, 0) x axis (0, 0, -1)
  line L1 (-15.1964, -47.6793) -> (-15.6964, -47.6793)
  line L2 (-11.7464, -37.8793) -> (-11.7464, -44.2293)
  line L3 (-15.6964, -34.4293) -> (-15.1964, -34.4293)
  line L4 (-19.1464, -44.2293) -> (-19.1464, -37.8793)
  arc A1 centre (-15.1964, -44.2293) radius 3.45 clockwise from (-11.7464, -44.2293) to (-15.1964, -47.6793)
  arc A2 centre (-15.1964, -37.8793) radius 3.45 clockwise from (-15.1964, -34.4293) to (-11.7464, -37.8793)
  arc A3 centre (-15.6964, -37.8793) radius 3.45 clockwise from (-19.1464, -37.8793) to (-15.6964, -34.4293)
  arc A4 centre (-15.6964, -44.2293) radius 3.45 clockwise from (-15.6964, -47.6793) to (-19.1464, -44.2293)
extrude "Extrude12" cut sketch "USB-C Full-Seating Local Wall Recess Sketch" blind -2.9527 (= "-( 2.952733 mm )") from offset 39.2
sketch "Sketch13" plane through (0, 0, 0) normal (1, 0, 0) x axis (0, 0, -1)
  line L1 (-15.3964, -45.7443) -> (-15.4964, -45.7443)
  line L2 (-13.0499, -38.7108) -> (-13.0499, -43.3978)
  line L3 (-15.4964, -36.3643) -> (-15.3964, -36.3643)
  line L4 (-17.8429, -43.3978) -> (-17.8429, -38.7108)
  arc A1 centre (-15.3964, -43.3978) radius 2.3465 clockwise from (-13.0499, -43.3978) to (-15.3964, -45.7443)
  arc A2 centre (-15.3964, -38.7108) radius 2.3465 clockwise from (-15.3964, -36.3643) to (-13.0499, -38.7108)
  arc A3 centre (-15.4964, -38.7108) radius 2.3465 clockwise from (-17.8429, -38.7108) to (-15.4964, -36.3643)
  arc A4 centre (-15.4964, -43.3978) radius 2.3465 clockwise from (-15.4964, -45.7443) to (-17.8429, -43.3978)
extrude "Extrude13" cut sketch "Sketch13" blind 40
sketch "PTT Internal Switch Body Clearance Sketch" plane through (0, 0, 0) normal (1, 0, 0) x axis (0, 0, -1)
  line L1 (-8.49, 6.65) -> (-18.01, 6.65)
  line L2 (-8.04, 16.9) -> (-8.04, 7.1)
  line L3 (-18.01, 17.35) -> (-8.49, 17.35)
  line L4 (-18.46, 7.1) -> (-18.46, 16.9)
  arc A1 centre (-8.49, 7.1) radius 0.45 clockwise from (-8.04, 7.1) to (-8.49, 6.65)
  arc A2 centre (-8.49, 16.9) radius 0.45 clockwise from (-8.49, 17.35) to (-8.04, 16.9)
  arc A3 centre (-18.01, 16.9) radius 0.45 clockwise from (-18.46, 16.9) to (-18.01, 17.35)
  arc A4 centre (-18.01, 7.1) radius 0.45 clockwise from (-18.01, 6.65) to (-18.46, 7.1)
extrude "Extrude14" cut sketch "PTT Internal Switch Body Clearance Sketch" blind 5.1 from offset 31.9
sketch "PTT Switch Cage Anchor Sketch" plane through (0, 0, 0) normal (0, 0, 1) x axis (1, 0, 0)
  line L1 (32, 6.45) -> (31.5, 6.45)
  line L2 (32.35, 7.3) -> (32.35, 6.8)
  line L3 (31.5, 7.65) -> (32, 7.65)
  line L4 (31.15, 6.8) -> (31.15, 7.3)
  arc A1 centre (32, 6.8) radius 0.35 clockwise from (32.35, 6.8) to (32, 6.45)
  arc A2 centre (32, 7.3) radius 0.35 clockwise from (32, 7.65) to (32.35, 7.3)
  arc A3 centre (31.5, 7.3) radius 0.35 clockwise from (31.15, 7.3) to (31.5, 7.65)
  arc A4 centre (31.5, 6.8) radius 0.35 clockwise from (31.5, 6.45) to (31.15, 6.8)
extrude "Extrude15" add sketch "PTT Switch Cage Anchor Sketch" blind 2.99 from offset 18.91
sketch "PTT Switch Cage Anchor Sketch (1)" plane through (0, 0, 0) normal (0, 0, 1) x axis (1, 0, 0)
  line L1 (32, 16.35) -> (31.5, 16.35)
  line L2 (32.35, 17.2) -> (32.35, 16.7)
  line L3 (31.5, 17.55) -> (32, 17.55)
  line L4 (31.15, 16.7) -> (31.15, 17.2)
  arc A1 centre (32, 16.7) radius 0.35 clockwise from (32.35, 16.7) to (32, 16.35)
  arc A2 centre (32, 17.2) radius 0.35 clockwise from (32, 17.55) to (32.35, 17.2)
  arc A3 centre (31.5, 17.2) radius 0.35 clockwise from (31.15, 17.2) to (31.5, 17.55)
  arc A4 centre (31.5, 16.7) radius 0.35 clockwise from (31.5, 16.35) to (31.15, 16.7)
extrude "Extrude16" add sketch "PTT Switch Cage Anchor Sketch (1)" blind 2.99 from offset 18.91
sketch "PTT Switch Roof Sketch" plane through (0, 0, 0) normal (0, 0, 1) x axis (1, 0, 0)
  line L1 (36.65, 6.65) -> (31.55, 6.65)
  line L2 (37.1, 16.9) -> (37.1, 7.1)
  line L3 (31.55, 17.35) -> (36.65, 17.35)
  line L4 (31.1, 7.1) -> (31.1, 16.9)
  arc A1 centre (36.65, 7.1) radius 0.45 clockwise from (37.1, 7.1) to (36.65, 6.65)
  arc A2 centre (36.65, 16.9) radius 0.45 clockwise from (36.65, 17.35) to (37.1, 16.9)
  arc A3 centre (31.55, 16.9) radius 0.45 clockwise from (31.1, 16.9) to (31.55, 17.35)
  arc A4 centre (31.55, 7.1) radius 0.45 clockwise from (31.55, 6.65) to (31.1, 7.1)
extrude "Extrude17" add sketch "PTT Switch Roof Sketch" blind 0.55 from offset 18.46
sketch "PTT Switch Inward Backstop Sketch" plane through (0, 0, 0) normal (0, 0, 1) x axis (1, 0, 0)
  line L1 (31.85, 6.65) -> (31.65, 6.65)
  line L2 (32.2, 17) -> (32.2, 7)
  line L3 (31.65, 17.35) -> (31.85, 17.35)
  line L4 (31.3, 7) -> (31.3, 17)
  arc A1 centre (31.85, 7) radius 0.35 clockwise from (32.2, 7) to (31.85, 6.65)
  arc A2 centre (31.85, 17) radius 0.35 clockwise from (31.85, 17.35) to (32.2, 17)
  arc A3 centre (31.65, 17) radius 0.35 clockwise from (31.3, 17) to (31.65, 17.35)
  arc A4 centre (31.65, 7) radius 0.35 clockwise from (31.65, 6.65) to (31.3, 7)
extrude "Extrude18" add sketch "PTT Switch Inward Backstop Sketch" blind 7.01 from offset 12
sketch "PTT Switch Side Rail Sketch" plane through (0, 0, 0) normal (0, 0, 1) x axis (1, 0, 0)
  line L1 (36.675, 6.65) -> (32.325, 6.65)
  line L2 (36.975, 7.15) -> (36.975, 6.95)
  line L3 (32.325, 7.45) -> (36.675, 7.45)
  line L4 (32.025, 6.95) -> (32.025, 7.15)
  arc A1 centre (36.675, 6.95) radius 0.3 clockwise from (36.975, 6.95) to (36.675, 6.65)
  arc A2 centre (36.675, 7.15) radius 0.3 clockwise from (36.675, 7.45) to (36.975, 7.15)
  arc A3 centre (32.325, 7.15) radius 0.3 clockwise from (32.025, 7.15) to (32.325, 7.45)
  arc A4 centre (32.325, 6.95) radius 0.3 clockwise from (32.325, 6.65) to (32.025, 6.95)
extrude "Extrude19" add sketch "PTT Switch Side Rail Sketch" blind 7.01 from offset 12
sketch "PTT Switch Side Rail Sketch (1)" plane through (0, 0, 0) normal (0, 0, 1) x axis (1, 0, 0)
  line L1 (36.675, 16.55) -> (32.325, 16.55)
  line L2 (36.975, 17.05) -> (36.975, 16.85)
  line L3 (32.325, 17.35) -> (36.675, 17.35)
  line L4 (32.025, 16.85) -> (32.025, 17.05)
  arc A1 centre (36.675, 16.85) radius 0.3 clockwise from (36.975, 16.85) to (36.675, 16.55)
  arc A2 centre (36.675, 17.05) radius 0.3 clockwise from (36.675, 17.35) to (36.975, 17.05)
  arc A3 centre (32.325, 17.05) radius 0.3 clockwise from (32.025, 17.05) to (32.325, 17.35)
  arc A4 centre (32.325, 16.85) radius 0.3 clockwise from (32.325, 16.55) to (32.025, 16.85)
extrude "Extrude20" add sketch "PTT Switch Side Rail Sketch (1)" blind 7.01 from offset 12
sketch "PTT Switch Actuator Shoulder Sketch" plane through (0, 0, 0) normal (0, 0, 1) x axis (1, 0, 0)
  line L1 (37.28, 6.65) -> (37.22, 6.65)
  line L2 (37.5, 17.13) -> (37.5, 6.87)
  line L3 (37.22, 17.35) -> (37.28, 17.35)
  line L4 (37, 6.87) -> (37, 17.13)
  arc A1 centre (37.28, 6.87) radius 0.22 clockwise from (37.5, 6.87) to (37.28, 6.65)
  arc A2 centre (37.28, 17.13) radius 0.22 clockwise from (37.28, 17.35) to (37.5, 17.13)
  arc A3 centre (37.22, 17.13) radius 0.22 clockwise from (37, 17.13) to (37.22, 17.35)
  arc A4 centre (37.22, 6.87) radius 0.22 clockwise from (37.22, 6.65) to (37, 6.87)
extrude "Extrude21" add sketch "PTT Switch Actuator Shoulder Sketch" blind 7.01 from offset 12
sketch "PTT Actuator Passage Sketch" plane through (0, 0, 0) normal (1, 0, 0) x axis (0, 0, -1)
  line L1 (-14.4, 10.6) -> (-16, 10.6)
  line L2 (-13.8, 12.8) -> (-13.8, 11.2)
  line L3 (-16, 13.4) -> (-14.4, 13.4)
  line L4 (-16.6, 11.2) -> (-16.6, 12.8)
  arc A1 centre (-14.4, 11.2) radius 0.6 clockwise from (-13.8, 11.2) to (-14.4, 10.6)
  arc A2 centre (-14.4, 12.8) radius 0.6 clockwise from (-14.4, 13.4) to (-13.8, 12.8)
  arc A3 centre (-16, 12.8) radius 0.6 clockwise from (-16.6, 12.8) to (-16, 13.4)
  arc A4 centre (-16, 11.2) radius 0.6 clockwise from (-16, 10.6) to (-16.6, 11.2)
extrude "Extrude22" cut sketch "PTT Actuator Passage Sketch" blind 4.2 from offset 35.8
sketch "Volume Up Internal Switch Body Clearance Sketch" plane through (0, 0, 0) normal (1, 0, 0) x axis (0, 0, -1)
  line L1 (-8.49, 17.65) -> (-18.01, 17.65)
  line L2 (-8.04, 27.9) -> (-8.04, 18.1)
  line L3 (-18.01, 28.35) -> (-8.49, 28.35)
  line L4 (-18.46, 18.1) -> (-18.46, 27.9)
  arc A1 centre (-8.49, 18.1) radius 0.45 clockwise from (-8.04, 18.1) to (-8.49, 17.65)
  arc A2 centre (-8.49, 27.9) radius 0.45 clockwise from (-8.49, 28.35) to (-8.04, 27.9)
  arc A3 centre (-18.01, 27.9) radius 0.45 clockwise from (-18.46, 27.9) to (-18.01, 28.35)
  arc A4 centre (-18.01, 18.1) radius 0.45 clockwise from (-18.01, 17.65) to (-18.46, 18.1)
extrude "Extrude23" cut sketch "Volume Up Internal Switch Body Clearance Sketch" blind -5.1 (= "-( 5.10 mm )") from offset -31.9
sketch "Volume Up Switch Cage Anchor Sketch" plane through (0, 0, 0) normal (0, 0, 1) x axis (1, 0, 0)
  line L1 (-31.5, 17.45) -> (-32, 17.45)
  line L2 (-31.15, 18.3) -> (-31.15, 17.8)
  line L3 (-32, 18.65) -> (-31.5, 18.65)
  line L4 (-32.35, 17.8) -> (-32.35, 18.3)
  arc A1 centre (-31.5, 17.8) radius 0.35 clockwise from (-31.15, 17.8) to (-31.5, 17.45)
  arc A2 centre (-31.5, 18.3) radius 0.35 clockwise from (-31.5, 18.65) to (-31.15, 18.3)
  arc A3 centre (-32, 18.3) radius 0.35 clockwise from (-32.35, 18.3) to (-32, 18.65)
  arc A4 centre (-32, 17.8) radius 0.35 clockwise from (-32, 17.45) to (-32.35, 17.8)
extrude "Extrude24" add sketch "Volume Up Switch Cage Anchor Sketch" blind 2.99 from offset 18.91
sketch "Volume Up Switch Cage Anchor Sketch (1)" plane through (0, 0, 0) normal (0, 0, 1) x axis (1, 0, 0)
  line L1 (-31.5, 27.35) -> (-32, 27.35)
  line L2 (-31.15, 28.2) -> (-31.15, 27.7)
  line L3 (-32, 28.55) -> (-31.5, 28.55)
  line L4 (-32.35, 27.7) -> (-32.35, 28.2)
  arc A1 centre (-31.5, 27.7) radius 0.35 clockwise from (-31.15, 27.7) to (-31.5, 27.35)
  arc A2 centre (-31.5, 28.2) radius 0.35 clockwise from (-31.5, 28.55) to (-31.15, 28.2)
  arc A3 centre (-32, 28.2) radius 0.35 clockwise from (-32.35, 28.2) to (-32, 28.55)
  arc A4 centre (-32, 27.7) radius 0.35 clockwise from (-32, 27.35) to (-32.35, 27.7)
extrude "Extrude25" add sketch "Volume Up Switch Cage Anchor Sketch (1)" blind 2.99 from offset 18.91
sketch "Volume Up Switch Roof Sketch" plane through (0, 0, 0) normal (0, 0, 1) x axis (1, 0, 0)
  line L1 (-31.55, 17.65) -> (-36.65, 17.65)
  line L2 (-31.1, 27.9) -> (-31.1, 18.1)
  line L3 (-36.65, 28.35) -> (-31.55, 28.35)
  line L4 (-37.1, 18.1) -> (-37.1, 27.9)
  arc A1 centre (-31.55, 18.1) radius 0.45 clockwise from (-31.1, 18.1) to (-31.55, 17.65)
  arc A2 centre (-31.55, 27.9) radius 0.45 clockwise from (-31.55, 28.35) to (-31.1, 27.9)
  arc A3 centre (-36.65, 27.9) radius 0.45 clockwise from (-37.1, 27.9) to (-36.65, 28.35)
  arc A4 centre (-36.65, 18.1) radius 0.45 clockwise from (-36.65, 17.65) to (-37.1, 18.1)
extrude "Extrude26" add sketch "Volume Up Switch Roof Sketch" blind 0.55 from offset 18.46
sketch "Volume Up Switch Inward Backstop Sketch" plane through (0, 0, 0) normal (0, 0, 1) x axis (1, 0, 0)
  line L1 (-31.65, 17.65) -> (-31.85, 17.65)
  line L2 (-31.3, 28) -> (-31.3, 18)
  line L3 (-31.85, 28.35) -> (-31.65, 28.35)
  line L4 (-32.2, 18) -> (-32.2, 28)
  arc A1 centre (-31.65, 18) radius 0.35 clockwise from (-31.3, 18) to (-31.65, 17.65)
  arc A2 centre (-31.65, 28) radius 0.35 clockwise from (-31.65, 28.35) to (-31.3, 28)
  arc A3 centre (-31.85, 28) radius 0.35 clockwise from (-32.2, 28) to (-31.85, 28.35)
  arc A4 centre (-31.85, 18) radius 0.35 clockwise from (-31.85, 17.65) to (-32.2, 18)
extrude "Extrude27" add sketch "Volume Up Switch Inward Backstop Sketch" blind 7.01 from offset 12
sketch "Volume Up Switch Side Rail Sketch" plane through (0, 0, 0) normal (0, 0, 1) x axis (1, 0, 0)
  line L1 (-32.325, 17.65) -> (-36.675, 17.65)
  line L2 (-32.025, 18.15) -> (-32.025, 17.95)
  line L3 (-36.675, 18.45) -> (-32.325, 18.45)
  line L4 (-36.975, 17.95) -> (-36.975, 18.15)
  arc A1 centre (-32.325, 17.95) radius 0.3 clockwise from (-32.025, 17.95) to (-32.325, 17.65)
  arc A2 centre (-32.325, 18.15) radius 0.3 clockwise from (-32.325, 18.45) to (-32.025, 18.15)
  arc A3 centre (-36.675, 18.15) radius 0.3 clockwise from (-36.975, 18.15) to (-36.675, 18.45)
  arc A4 centre (-36.675, 17.95) radius 0.3 clockwise from (-36.675, 17.65) to (-36.975, 17.95)
extrude "Extrude28" add sketch "Volume Up Switch Side Rail Sketch" blind 7.01 from offset 12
